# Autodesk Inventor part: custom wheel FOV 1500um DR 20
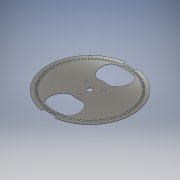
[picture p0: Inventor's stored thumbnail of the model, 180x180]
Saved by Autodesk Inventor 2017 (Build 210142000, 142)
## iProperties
Created: 2016-09
Part Number: custom wheel FOV 1500um DR 20
Material: Generic
Document SubType Name: Modeling
Designer: Radek
Density: 1 g/cm^3
Appearance: Mirror
Author: Radek
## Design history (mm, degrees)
workplane "Work Plane1"
sketch "Sketch1"
  geometry: L1 (-46.781, 4.422)-(-44.253, 4.183) reference; L2 (-44.362, 2.791)-(-46.897, 2.951) reference; L3 (-46.411, 7.351)-(-43.903, 6.954) reference; L4 (-44.099, 5.571)-(-46.619, 5.889) reference; L5 (-45.858, 10.251)-(-43.38, 9.696) reference; L6 (-43.663, 8.329)-(-46.158, 8.805) reference; L7 (-45.124, 13.11)-(-42.685, 12.401) reference; L8 (-43.054, 11.054)-(-45.514, 11.686) reference; L9 (-44.212, 15.917)-(-41.822, 15.057) reference; L10 (-42.274, 13.736)-(-44.69, 14.521) reference; L11 (-43.125, 18.662)-(-40.794, 17.653) reference; L12 (-41.329, 16.363)-(-43.69, 17.298) reference; L13 (-41.868, 21.333)-(-39.605, 20.18) reference; L14 (-40.22, 18.926)-(-42.518, 20.007) reference; L15 (-40.446, 23.92)-(-38.26, 22.627) reference; L16 (-38.952, 21.414)-(-41.178, 22.638) reference; L17 (-38.865, 26.412)-(-36.764, 24.985) reference; L18 (-37.53, 23.818)-(-39.675, 25.179) reference; L19 (-37.129, 28.801)-(-35.122, 27.244) reference; L20 (-35.961, 26.127)-(-38.016, 27.62) reference; L21 (-35.248, 31.075)-(-33.342, 29.395) reference; L22 (-34.249, 28.333)-(-36.206, 29.953) reference; L23 (-33.227, 33.227)-(-31.431, 31.431) reference; L24 (-32.403, 30.428)-(-34.254, 32.167) reference; L25 (-31.075, 35.248)-(-29.395, 33.342) reference; L26 (-30.428, 32.403)-(-32.167, 34.254) reference; L27 (-28.801, 37.129)-(-27.244, 35.122) reference; L28 (-28.333, 34.249)-(-29.953, 36.206) reference; L29 (-26.412, 38.865)-(-24.985, 36.764) reference; L30 (-26.127, 35.961)-(-27.62, 38.016) reference; L31 (-23.92, 40.446)-(-22.627, 38.26) reference; L32 (-23.818, 37.53)-(-25.179, 39.675) reference; L33 (-21.333, 41.868)-(-20.18, 39.605) reference; L34 (-21.414, 38.952)-(-22.638, 41.178) reference; L35 (-18.662, 43.125)-(-17.653, 40.794) reference; L36 (-18.926, 40.22)-(-20.007, 42.518) reference; L37 (-15.917, 44.212)-(-15.057, 41.822) reference; L38 (-16.363, 41.329)-(-17.298, 43.69) reference; L39 (-13.11, 45.124)-(-12.401, 42.685) reference; L40 (-13.736, 42.274)-(-14.521, 44.69) reference; L41 (-10.251, 45.858)-(-9.696, 43.38) reference; L42 (-11.054, 43.054)-(-11.686, 45.514) reference; L43 (-7.351, 46.411)-(-6.954, 43.903) reference; L44 (-8.329, 43.663)-(-8.805, 46.158) reference; L45 (-4.422, 46.781)-(-4.183, 44.253) reference; L46 (-5.571, 44.099)-(-5.889, 46.619) reference; L47 (-1.476, 46.967)-(-1.396, 44.428) reference; L48 (-2.791, 44.362)-(-2.951, 46.897) reference; L49 (1.476, 46.967)-(1.396, 44.428) reference; L50 (0, 44.45)-(0, 46.99) reference; L51 (4.422, 46.781)-(4.183, 44.253) reference; L52 (2.791, 44.362)-(2.951, 46.897) reference; L53 (7.351, 46.411)-(6.954, 43.903) reference; L54 (5.571, 44.099)-(5.889, 46.619) reference; L55 (10.251, 45.858)-(9.696, 43.38) reference; L56 (8.329, 43.663)-(8.805, 46.158) reference; L57 (13.11, 45.124)-(12.401, 42.685) reference; L58 (11.054, 43.054)-(11.686, 45.514) reference; L59 (15.917, 44.212)-(15.057, 41.822) reference; L60 (13.736, 42.274)-(14.521, 44.69) reference; L61 (18.662, 43.125)-(17.653, 40.794) reference; L62 (16.363, 41.329)-(17.298, 43.69) reference; L63 (21.333, 41.868)-(20.18, 39.605) reference; L64 (18.926, 40.22)-(20.007, 42.518) reference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; C1 r 50.8 at (0, 0) reference; C2 r 2.984 at (0, 0) reference; C3 r 1.524 at (0, 6.553) reference; C4 r 1.524 at (10.339, 5.969) reference; C5 r 2.984 at (0, 0) reference; C6 r 1.524 at (0, -11.938) reference; C7 r 1.524 at (-5.675, -3.277) reference; C8 r 1.524 at (-10.339, 5.969) reference; C9 r 1.524 at (5.675, -3.277) reference; C10 r 50.8 at (0, 0) reference; C11 r 1.524 at (-5.675, -3.277) reference; C12 r 1.524 at (-10.339, 5.969) reference; C13 r 1.524 at (0, 6.553) reference; C14 r 1.524 at (10.339, 5.969) reference; C15 r 1.524 at (5.675, -3.277) reference; C16 r 1.524 at (0, -11.938) reference; C17 r 2.984 at (0, 0) reference; A1 r 17.081 centre (0, 0) between (0, -17.081) and (17.081, 0) reference; A2 r 17.081 centre (0, 0) between (0, 17.081) and (-17.081, 0) reference; A3 r 43.18 centre (0, 0) between (0, 43.18) and (-43.18, 0) reference; A4 r 43.18 centre (0, 0) between (0, -43.18) and (43.18, 0) reference; A5 r 44.45 centre (0, 0) between (-44.253, 4.183) and (-44.362, 2.791) reference; A6 r 46.99 centre (0, 0) between (-46.781, 4.422) and (-46.897, 2.951) reference; A7 r 44.45 centre (0, 0) between (-43.903, 6.954) and (-44.099, 5.571) reference; A8 r 46.99 centre (0, 0) between (-46.411, 7.351) and (-46.619, 5.889) reference; A9 r 44.45 centre (0, 0) between (-43.38, 9.696) and (-43.663, 8.329) reference; A10 r 46.99 centre (0, 0) between (-45.858, 10.251) and (-46.158, 8.805) reference; A11 r 44.45 centre (0, 0) between (-42.685, 12.401) and (-43.054, 11.054) reference; A12 r 46.99 centre (0, 0) between (-45.124, 13.11) and (-45.514, 11.686) reference; A13 r 44.45 centre (0, 0) between (-41.822, 15.057) and (-42.274, 13.736) reference; A14 r 46.99 centre (0, 0) between (-44.212, 15.917) and (-44.69, 14.521) reference; A15 r 44.45 centre (0, 0) between (-40.794, 17.653) and (-41.329, 16.363) reference; A16 r 46.99 centre (0, 0) between (-43.125, 18.662) and (-43.69, 17.298) reference; A17 r 44.45 centre (0, 0) between (-39.605, 20.18) and (-40.22, 18.926) reference; A18 r 46.99 centre (0, 0) between (-41.868, 21.333) and (-42.518, 20.007) reference; A19 r 44.45 centre (0, 0) between (-38.26, 22.627) and (-38.952, 21.414) reference; A20 r 46.99 centre (0, 0) between (-40.446, 23.92) and (-41.178, 22.638) reference; A21 r 44.45 centre (0, 0) between (-36.764, 24.985) and (-37.53, 23.818) reference; A22 r 46.99 centre (0, 0) between (-38.865, 26.412) and (-39.675, 25.179) reference; A23 r 44.45 centre (0, 0) between (-35.122, 27.244) and (-35.961, 26.127) reference; A24 r 46.99 centre (0, 0) between (-37.129, 28.801) and (-38.016, 27.62) reference; A25 r 44.45 centre (0, 0) between (-33.342, 29.395) and (-34.249, 28.333) reference; A26 r 46.99 centre (0, 0) between (-35.248, 31.075) and (-36.206, 29.953) reference; A27 r 44.45 centre (0, 0) between (-31.431, 31.431) and (-32.403, 30.428) reference; A28 r 46.99 centre (0, 0) between (-33.227, 33.227) and (-34.254, 32.167) reference; A29 r 44.45 centre (0, 0) between (-29.395, 33.342) and (-30.428, 32.403) reference; A30 r 46.99 centre (0, 0) between (-31.075, 35.248) and (-32.167, 34.254) reference; A31 r 44.45 centre (0, 0) between (-27.244, 35.122) and (-28.333, 34.249) reference; A32 r 46.99 centre (0, 0) between (-28.801, 37.129) and (-29.953, 36.206) reference; A33 r 44.45 centre (0, 0) between (-24.985, 36.764) and (-26.127, 35.961) reference; A34 r 46.99 centre (0, 0) between (-26.412, 38.865) and (-27.62, 38.016) reference; A35 r 44.45 centre (0, 0) between (-22.627, 38.26) and (-23.818, 37.53) reference; A36 r 46.99 centre (0, 0) between (-23.92, 40.446) and (-25.179, 39.675) reference; A37 r 44.45 centre (0, 0) between (-20.18, 39.605) and (-21.414, 38.952) reference; A38 r 46.99 centre (0, 0) between (-21.333, 41.868) and (-22.638, 41.178) reference; A39 r 44.45 centre (0, 0) between (-17.653, 40.794) and (-18.926, 40.22) reference; A40 r 46.99 centre (0, 0) between (-18.662, 43.125) and (-20.007, 42.518) reference; A41 r 44.45 centre (0, 0) between (-15.057, 41.822) and (-16.363, 41.329) reference; A42 r 46.99 centre (0, 0) between (-15.917, 44.212) and (-17.298, 43.69) reference; A43 r 44.45 centre (0, 0) between (-12.401, 42.685) and (-13.736, 42.274) reference; A44 r 46.99 centre (0, 0) between (-13.11, 45.124) and (-14.521, 44.69) reference; A45 r 44.45 centre (0, 0) between (-9.696, 43.38) and (-11.054, 43.054) reference; A46 r 46.99 centre (0, 0) between (-10.251, 45.858) and (-11.686, 45.514) reference; A47 r 44.45 centre (0, 0) between (-6.954, 43.903) and (-8.329, 43.663) reference; A48 r 46.99 centre (0, 0) between (-7.351, 46.411) and (-8.805, 46.158) reference; A49 r 44.45 centre (0, 0) between (-4.183, 44.253) and (-5.571, 44.099) reference; A50 r 46.99 centre (0, 0) between (-4.422, 46.781) and (-5.889, 46.619) reference; A51 r 44.45 centre (0, 0) between (-1.396, 44.428) and (-2.791, 44.362) reference; A52 r 46.99 centre (0, 0) between (-1.476, 46.967) and (-2.951, 46.897) reference; A53 r 44.45 centre (0, 0) between (1.396, 44.428) and (0, 44.45) reference; A54 r 46.99 centre (0, 0) between (1.476, 46.967) and (0, 46.99) reference; A55 r 44.45 centre (0, 0) between (4.183, 44.253) and (2.791, 44.362) reference; A56 r 46.99 centre (0, 0) between (4.422, 46.781) and (2.951, 46.897) reference; A57 r 44.45 centre (0, 0) between (6.954, 43.903) and (5.571, 44.099) reference; A58 r 46.99 centre (0, 0) between (7.351, 46.411) and (5.889, 46.619) reference; A59 r 44.45 centre (0, 0) between (9.696, 43.38) and (8.329, 43.663) reference; A60 r 46.99 centre (0, 0) between (10.251, 45.858) and (8.805, 46.158) reference; A61 r 44.45 centre (0, 0) between (12.401, 42.685) and (11.054, 43.054) reference; A62 r 46.99 centre (0, 0) between (13.11, 45.124) and (11.686, 45.514) reference; A63 r 44.45 centre (0, 0) between (15.057, 41.822) and (13.736, 42.274) reference; A64 r 46.99 centre (0, 0) between (15.917, 44.212) and (14.521, 44.69) reference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; 1 further point
  constraints: 8 end point, 2 collinear, 1 parallel
extrude "Extrusion2" new body sketch "Sketch1" distance "d2" = 0.3; taper "d3" = 0 deg
sketch "Sketch2"
  geometry: L1 (-46.781, 4.422)-(-44.253, 4.183) reference; L2 (-44.362, 2.791)-(-46.897, 2.951) reference; L3 (-46.411, 7.351)-(-43.903, 6.954) reference; L4 (-44.099, 5.571)-(-46.619, 5.889) reference; L5 (-45.858, 10.251)-(-43.38, 9.696) reference; L6 (-43.663, 8.329)-(-46.158, 8.805) reference; L7 (-45.124, 13.11)-(-42.685, 12.401) reference; L8 (-43.054, 11.054)-(-45.514, 11.686) reference; L9 (-44.212, 15.917)-(-41.822, 15.057) reference; L10 (-42.274, 13.736)-(-44.69, 14.521) reference; L11 (-43.125, 18.662)-(-40.794, 17.653) reference; L12 (-41.329, 16.363)-(-43.69, 17.298) reference; L13 (-41.868, 21.333)-(-39.605, 20.18) reference; L14 (-40.22, 18.926)-(-42.518, 20.007) reference; L15 (-40.446, 23.92)-(-38.26, 22.627) reference; L16 (-38.952, 21.414)-(-41.178, 22.638) reference; L17 (-38.865, 26.412)-(-36.764, 24.985) reference; L18 (-37.53, 23.818)-(-39.675, 25.179) reference; L19 (-37.129, 28.801)-(-35.122, 27.244) reference; L20 (-35.961, 26.127)-(-38.016, 27.62) reference; L21 (-35.248, 31.075)-(-33.342, 29.395) reference; L22 (-34.249, 28.333)-(-36.206, 29.953) reference; L23 (-33.227, 33.227)-(-31.431, 31.431) reference; L24 (-32.403, 30.428)-(-34.254, 32.167) reference; L25 (-31.075, 35.248)-(-29.395, 33.342) reference; L26 (-30.428, 32.403)-(-32.167, 34.254) reference; L27 (-28.801, 37.129)-(-27.244, 35.122) reference; L28 (-28.333, 34.249)-(-29.953, 36.206) reference; L29 (-26.412, 38.865)-(-24.985, 36.764) reference; L30 (-26.127, 35.961)-(-27.62, 38.016) reference; L31 (-23.92, 40.446)-(-22.627, 38.26) reference; L32 (-23.818, 37.53)-(-25.179, 39.675) reference; L33 (-21.333, 41.868)-(-20.18, 39.605) reference; L34 (-21.414, 38.952)-(-22.638, 41.178) reference; L35 (-18.662, 43.125)-(-17.653, 40.794) reference; L36 (-18.926, 40.22)-(-20.007, 42.518) reference; L37 (-15.917, 44.212)-(-15.057, 41.822) reference; L38 (-16.363, 41.329)-(-17.298, 43.69) reference; L39 (-13.11, 45.124)-(-12.401, 42.685) reference; L40 (-13.736, 42.274)-(-14.521, 44.69) reference; L41 (-10.251, 45.858)-(-9.696, 43.38) reference; L42 (-11.054, 43.054)-(-11.686, 45.514) reference; L43 (-7.351, 46.411)-(-6.954, 43.903) reference; L44 (-8.329, 43.663)-(-8.805, 46.158) reference; L45 (-4.422, 46.781)-(-4.183, 44.253) reference; L46 (-5.571, 44.099)-(-5.889, 46.619) reference; L47 (-1.476, 46.967)-(-1.396, 44.428) reference; L48 (-2.791, 44.362)-(-2.951, 46.897) reference; L49 (1.476, 46.967)-(1.396, 44.428) reference; L50 (0, 44.45)-(0, 46.99) reference; L51 (4.422, 46.781)-(4.183, 44.253) reference; L52 (2.791, 44.362)-(2.951, 46.897) reference; L53 (7.351, 46.411)-(6.954, 43.903) reference; L54 (5.571, 44.099)-(5.889, 46.619) reference; L55 (10.251, 45.858)-(9.696, 43.38) reference; L56 (8.329, 43.663)-(8.805, 46.158) reference; L57 (13.11, 45.124)-(12.401, 42.685) reference; L58 (11.054, 43.054)-(11.686, 45.514) reference; L59 (15.917, 44.212)-(15.057, 41.822) reference; L60 (13.736, 42.274)-(14.521, 44.69) reference; L61 (18.662, 43.125)-(17.653, 40.794) reference; L62 (16.363, 41.329)-(17.298, 43.69) reference; L63 (21.333, 41.868)-(20.18, 39.605) reference; L64 (18.926, 40.22)-(20.007, 42.518) reference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; C1 r 50.8 at (0, 0) reference; C2 r 1.524 at (-5.675, -3.277) reference; C3 r 1.524 at (-10.339, 5.969) reference; C4 r 1.524 at (0, 6.553) reference; C5 r 1.524 at (10.339, 5.969) reference; C6 r 1.524 at (5.675, -3.277) reference; C7 r 1.524 at (0, -11.938) reference; C8 r 2.984 at (0, 0) reference; A1 r 44.45 centre (0, 0) between (-44.253, 4.183) and (-44.362, 2.791) reference; A2 r 46.99 centre (0, 0) between (-46.781, 4.422) and (-46.897, 2.951) reference; A3 r 44.45 centre (0, 0) between (-43.903, 6.954) and (-44.099, 5.571) reference; A4 r 46.99 centre (0, 0) between (-46.411, 7.351) and (-46.619, 5.889) reference; A5 r 44.45 centre (0, 0) between (-43.38, 9.696) and (-43.663, 8.329) reference; A6 r 46.99 centre (0, 0) between (-45.858, 10.251) and (-46.158, 8.805) reference; A7 r 44.45 centre (0, 0) between (-42.685, 12.401) and (-43.054, 11.054) reference; A8 r 46.99 centre (0, 0) between (-45.124, 13.11) and (-45.514, 11.686) reference; A9 r 44.45 centre (0, 0) between (-41.822, 15.057) and (-42.274, 13.736) reference; A10 r 46.99 centre (0, 0) between (-44.212, 15.917) and (-44.69, 14.521) reference; A11 r 44.45 centre (0, 0) between (-40.794, 17.653) and (-41.329, 16.363) reference; A12 r 46.99 centre (0, 0) between (-43.125, 18.662) and (-43.69, 17.298) reference; A13 r 44.45 centre (0, 0) between (-39.605, 20.18) and (-40.22, 18.926) reference; A14 r 46.99 centre (0, 0) between (-41.868, 21.333) and (-42.518, 20.007) reference; A15 r 44.45 centre (0, 0) between (-38.26, 22.627) and (-38.952, 21.414) reference; A16 r 46.99 centre (0, 0) between (-40.446, 23.92) and (-41.178, 22.638) reference; A17 r 44.45 centre (0, 0) between (-36.764, 24.985) and (-37.53, 23.818) reference; A18 r 46.99 centre (0, 0) between (-38.865, 26.412) and (-39.675, 25.179) reference; A19 r 44.45 centre (0, 0) between (-35.122, 27.244) and (-35.961, 26.127) reference; A20 r 46.99 centre (0, 0) between (-37.129, 28.801) and (-38.016, 27.62) reference; A21 r 44.45 centre (0, 0) between (-33.342, 29.395) and (-34.249, 28.333) reference; A22 r 46.99 centre (0, 0) between (-35.248, 31.075) and (-36.206, 29.953) reference; A23 r 44.45 centre (0, 0) between (-31.431, 31.431) and (-32.403, 30.428) reference; A24 r 46.99 centre (0, 0) between (-33.227, 33.227) and (-34.254, 32.167) reference; A25 r 44.45 centre (0, 0) between (-29.395, 33.342) and (-30.428, 32.403) reference; A26 r 46.99 centre (0, 0) between (-31.075, 35.248) and (-32.167, 34.254) reference; A27 r 44.45 centre (0, 0) between (-27.244, 35.122) and (-28.333, 34.249) reference; A28 r 46.99 centre (0, 0) between (-28.801, 37.129) and (-29.953, 36.206) reference; A29 r 44.45 centre (0, 0) between (-24.985, 36.764) and (-26.127, 35.961) reference; A30 r 46.99 centre (0, 0) between (-26.412, 38.865) and (-27.62, 38.016) reference; A31 r 44.45 centre (0, 0) between (-22.627, 38.26) and (-23.818, 37.53) reference; A32 r 46.99 centre (0, 0) between (-23.92, 40.446) and (-25.179, 39.675) reference; A33 r 44.45 centre (0, 0) between (-20.18, 39.605) and (-21.414, 38.952) reference; A34 r 46.99 centre (0, 0) between (-21.333, 41.868) and (-22.638, 41.178) reference; A35 r 44.45 centre (0, 0) between (-17.653, 40.794) and (-18.926, 40.22) reference; A36 r 46.99 centre (0, 0) between (-18.662, 43.125) and (-20.007, 42.518) reference; A37 r 44.45 centre (0, 0) between (-15.057, 41.822) and (-16.363, 41.329) reference; A38 r 46.99 centre (0, 0) between (-15.917, 44.212) and (-17.298, 43.69) reference; A39 r 44.45 centre (0, 0) between (-12.401, 42.685) and (-13.736, 42.274) reference; A40 r 46.99 centre (0, 0) between (-13.11, 45.124) and (-14.521, 44.69) reference; A41 r 44.45 centre (0, 0) between (-9.696, 43.38) and (-11.054, 43.054) reference; A42 r 46.99 centre (0, 0) between (-10.251, 45.858) and (-11.686, 45.514) reference; A43 r 44.45 centre (0, 0) between (-6.954, 43.903) and (-8.329, 43.663) reference; A44 r 46.99 centre (0, 0) between (-7.351, 46.411) and (-8.805, 46.158) reference; A45 r 44.45 centre (0, 0) between (-4.183, 44.253) and (-5.571, 44.099) reference; A46 r 46.99 centre (0, 0) between (-4.422, 46.781) and (-5.889, 46.619) reference; A47 r 44.45 centre (0, 0) between (-1.396, 44.428) and (-2.791, 44.362) reference; A48 r 46.99 centre (0, 0) between (-1.476, 46.967) and (-2.951, 46.897) reference; A49 r 44.45 centre (0, 0) between (1.396, 44.428) and (0, 44.45) reference; A50 r 46.99 centre (0, 0) between (1.476, 46.967) and (0, 46.99) reference; A51 r 44.45 centre (0, 0) between (4.183, 44.253) and (2.791, 44.362) reference; A52 r 46.99 centre (0, 0) between (4.422, 46.781) and (2.951, 46.897) reference; A53 r 44.45 centre (0, 0) between (6.954, 43.903) and (5.571, 44.099) reference; A54 r 46.99 centre (0, 0) between (7.351, 46.411) and (5.889, 46.619) reference; A55 r 44.45 centre (0, 0) between (9.696, 43.38) and (8.329, 43.663) reference; A56 r 46.99 centre (0, 0) between (10.251, 45.858) and (8.805, 46.158) reference; A57 r 44.45 centre (0, 0) between (12.401, 42.685) and (11.054, 43.054) reference; A58 r 46.99 centre (0, 0) between (13.11, 45.124) and (11.686, 45.514) reference; A59 r 44.45 centre (0, 0) between (15.057, 41.822) and (13.736, 42.274) reference; A60 r 46.99 centre (0, 0) between (15.917, 44.212) and (14.521, 44.69) reference; A61 r 44.45 centre (0, 0) between (17.653, 40.794) and (16.363, 41.329) reference; A62 r 46.99 centre (0, 0) between (18.662, 43.125) and (17.298, 43.69) reference; A63 r 44.45 centre (0, 0) between (20.18, 39.605) and (18.926, 40.22) reference; A64 r 46.99 centre (0, 0) between (21.333, 41.868) and (20.007, 42.518) reference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; 1 further point
  constraints: 8 end point, 1 collinear
extrude "Extrusion3" cut sketch "Sketch2" stored distance "d4" = 0.254; taper "d5" = 0 deg
sketch "Sketch3" dims "d20" = 9.26667 (= 0.5 x holediameter), "d21" = 13.10505 (= 1.41421 x d20)
  geometry: L1 (-10.339, 5.969)-(10.339, 5.969); L2 (0, 0)-(50.8, 0); L3 (0, 44.45)-(0, 46.99) reference; L4 (0, 0)-(0, 50.8); L5 (0, 30)-(0, 16.895); L6 (0, 50.165)-(0, 48.26) reference; L7 (-48.26, 0)-(-50.165, 0) reference; L8 (0, 0)-(19.371, 28.772); L9 (0, 50.8)-(0, 50.165); L10 (4.373, 16.319)-(11.156, 41.636); L11 (-4.373, 16.319)-(-11.156, 41.636); C1 r 2.984 at (0, 0) reference; C2 r 15.25 at (0, 0); C3 r 1.524 at (-10.339, 5.969) reference; C4 r 1.524 at (0, -11.938) reference; C5 r 1.524 at (10.339, 5.969) reference; C6 r 1.524 at (-5.675, -3.277) reference; C7 r 1.524 at (5.675, -3.277) reference; A1 r 50.8 centre (0, 0) between (50.8, 0) and (0, 50.8) reference; A2 r 48.26 centre (0, 0) between (0, 48.26) and (-48.26, 0) reference; A3 r 50.165 centre (0, 0) between (0, 50.165) and (-50.165, 0) reference; A4 r 50.165 centre (0, 0) between (-20.154, -45.939) and (22.037, -45.066); A5 r 48.26 centre (0, 0) between (-19.033, -44.348) and (20.956, -43.472); 3 further points; 3 other entities
  constraints: 16 end point, 8 point on circle, 3 centre point, 3 coincident, 2 midpoint, 2 vertical, 1 collinear, 1 horizontal, 1 parallel, 1 point on line, 1 vertical alignment, 19 other
  dimensions: "d9" = 30.5 diameter of C2; "d18" = 0 distance between parallel lines of L4 L5; "d19" = 30 distance of point (0, 0) L5.start (= offaxis); "d24" = 15 deg dimension on point (0, 0) L5.start point (-7.765, 28.978) (= 0.5 x angle); "d28" = 15 deg dimension on point (0, 0) point (7.765, 28.978) L5.start (= 0.5 x angle); "d32" = 0.635 distance of L4.end L6.start (derived)
extrude "Extrusion7" cut sketch "Sketch3" stored distance "d40" = 10; taper "d41" = 0 deg
sketch "Sketch4"
  geometry: L1 (-11.156, 41.636)-(-4.373, 16.319) reference; L2 (4.373, 16.319)-(11.156, 41.636) reference; L3 (11.156, 41.636)-(4.373, 16.319) reference; L4 (-4.373, 16.319)-(-11.156, 41.636) reference; L5 (-4.373, 16.319)-(-11.156, 41.636); L6 (4.373, 16.319)-(11.156, 41.636); C1 r 2.984 at (0, 0) reference; C2 r 50.8 at (0, 0) reference; A1 r 16.895 centre (0, 0) between (4.373, 16.319) and (-4.373, 16.319); A2 r 43.105 centre (0, 0) between (11.156, 41.636) and (-11.156, 41.636); 3 further points; 2 other entities
  constraints: 4 end point, 4 point on circle, 2 centre point, 2 coincident, 2 collinear, 2 other
extrude "Extrusion8" cut sketch "Sketch4" stored distance "d42" = 10; taper "d43" = 0 deg
sketch "Sketch5"
  geometry: L1 (0, 0)-(-7.947, 50.175); L2 (0, 0)-(7.947, 50.175); L3 (7.524, 47.508)-(7.837, 49.483); L4 (-7.524, 47.508)-(-7.837, 49.483); L5 (6.954, 43.903)-(7.351, 46.411) reference; L6 (4.422, 46.781)-(4.183, 44.253) reference; L7 (7.351, 46.411)-(6.954, 43.903) reference; C1 r 2.984 at (0, 0) reference; A1 r 50.8 centre (0, 0) between (-7.947, 50.175) and (7.947, 50.175) reference; A2 r 16.895 centre (0, 0) between (4.373, 16.319) and (-4.373, 16.319) reference; A3 r 43.105 centre (0, 0) between (11.156, 41.636) and (-11.156, 41.636) reference; A4 r 48.1 centre (0, 0) between (7.524, 47.508) and (-7.524, 47.508); A5 r 50.1 centre (0, 0) between (7.837, 49.483) and (-7.837, 49.483); 4 further points; 2 other entities
  constraints: 8 end point, 6 point on circle, 3 point on line, 2 centre point, 2 coincident, 2 collinear, 1 midpoint, 8 other
  dimensions: "d44" = 0.7 radial gap between concentric circles of A1 A5; "d45" = 2 radial gap between concentric circles of A5 A4; "d53" = 18 deg angle of L1 L2
extrude "Extrusion9" cut sketch "Sketch5" stored distance "d46" = 10; taper "d47" = 0 deg
pattern_circular "Circular Pattern3" dims angle "d49" = 360 deg
sketch "Sketch6"
  geometry: L1 (16.895, 0)-(16.319, 0) reference; L2 (41.636, 0)-(43.105, 0) reference; L3 (16.319, -0.3)-(16.895, -0.3) reference; L4 (43.105, -0.3)-(41.636, -0.3) reference; L5 (-50.8, 0)-(50.8, 0) reference; L6 (-50.8, -0.3)-(50.8, -0.3) reference; L7 (16.895, 0)-(43.105, 0); L8 (16.895, -0.3)-(43.105, -0.3); L9 (30, -0.3)-(30, 0); L10 (30, -0.15)-(32.935, -3.085); 1 further point
  constraints: 8 end point, 3 midpoint, 1 collinear, 1 parallel
  dimensions: "d51" = 135 deg angle of L10 L9
workaxis "Work Axis1"
workplane "Work Plane3"
  workplane "Work Plane2"
sketch "Sketch7"
  geometry: L1 (0, -11.938)-(-10.339, 5.969); C1 r 1.524 at (0, -11.938) reference; C2 r 1.524 at (-10.339, 5.969) reference; C3 r 2.984 at (0, 0) reference; C4 r 10.414 at (0, 0); 2 further points
  constraints: 2 end point, 1 centre point, 1 coincident, 1 tangent, 1 other
extrude "Extrusion11" cut sketch "Sketch7" stored distance "d57" = 10; taper "d58" = 0 deg
sketch "Sketch8"
  geometry: L1 (7.524, -47.508)-(7.837, -49.483) reference; L2 (-7.837, -49.483)-(-7.524, -47.508) reference; L3 (7.837, 49.483)-(7.524, 47.508) reference; L4 (-7.524, 47.508)-(-7.837, 49.483) reference; L5 (-46.967, -1.476)-(-44.428, -1.396) reference; L6 (-44.428, -1.396)-(-44.362, -2.791) reference; L7 (-44.362, -2.791)-(-46.897, -2.951) reference; L8 (-46.897, -2.951)-(-46.967, -1.476) reference; L9 (-46.781, -4.422)-(-44.253, -4.183) reference; L10 (-44.253, -4.183)-(-44.099, -5.571) reference; L11 (-44.099, -5.571)-(-46.619, -5.889) reference; L12 (-46.619, -5.889)-(-46.781, -4.422) reference; L13 (-46.411, -7.351)-(-43.903, -6.954) reference; L14 (-43.903, -6.954)-(-43.663, -8.329) reference; L15 (-43.663, -8.329)-(-46.158, -8.805) reference; L16 (-46.158, -8.805)-(-46.411, -7.351) reference; L17 (-45.858, -10.251)-(-43.38, -9.696) reference; L18 (-43.38, -9.696)-(-43.054, -11.054) reference; L19 (-43.054, -11.054)-(-45.514, -11.686) reference; L20 (-45.514, -11.686)-(-45.858, -10.251) reference; L21 (-45.124, -13.11)-(-42.685, -12.401) reference; L22 (-42.685, -12.401)-(-42.274, -13.736) reference; L23 (-42.274, -13.736)-(-44.69, -14.521) reference; L24 (-44.69, -14.521)-(-45.124, -13.11) reference; L25 (-44.212, -15.917)-(-41.822, -15.057) reference; L26 (-41.822, -15.057)-(-41.329, -16.363) reference; L27 (-41.329, -16.363)-(-43.69, -17.298) reference; L28 (-43.69, -17.298)-(-44.212, -15.917) reference; L29 (-43.125, -18.662)-(-40.794, -17.653) reference; L30 (-40.794, -17.653)-(-40.22, -18.926) reference; L31 (-40.22, -18.926)-(-42.518, -20.007) reference; L32 (-42.518, -20.007)-(-43.125, -18.662) reference; L33 (-41.868, -21.333)-(-39.605, -20.18) reference; L34 (-39.605, -20.18)-(-38.952, -21.414) reference; L35 (-38.952, -21.414)-(-41.178, -22.638) reference; L36 (-41.178, -22.638)-(-41.868, -21.333) reference; L37 (-40.446, -23.92)-(-38.26, -22.627) reference; L38 (-38.26, -22.627)-(-37.53, -23.818) reference; L39 (-37.53, -23.818)-(-39.675, -25.179) reference; L40 (-39.675, -25.179)-(-40.446, -23.92) reference; L41 (-38.865, -26.412)-(-36.764, -24.985) reference; L42 (-36.764, -24.985)-(-35.961, -26.127) reference; L43 (-35.961, -26.127)-(-38.016, -27.62) reference; L44 (-38.016, -27.62)-(-38.865, -26.412) reference; L45 (-37.129, -28.801)-(-35.122, -27.244) reference; L46 (-35.122, -27.244)-(-34.249, -28.333) reference; L47 (-34.249, -28.333)-(-36.206, -29.953) reference; L48 (-36.206, -29.953)-(-37.129, -28.801) reference; L49 (-35.248, -31.075)-(-33.342, -29.395) reference; L50 (-33.342, -29.395)-(-32.403, -30.428) reference; L51 (-32.403, -30.428)-(-34.254, -32.167) reference; L52 (-34.254, -32.167)-(-35.248, -31.075) reference; L53 (-33.227, -33.227)-(-31.431, -31.431) reference; L54 (-31.431, -31.431)-(-30.428, -32.403) reference; L55 (-30.428, -32.403)-(-32.167, -34.254) reference; L56 (-32.167, -34.254)-(-33.227, -33.227) reference; L57 (-31.075, -35.248)-(-29.395, -33.342) reference; L58 (-29.395, -33.342)-(-28.333, -34.249) reference; L59 (-28.333, -34.249)-(-29.953, -36.206) reference; L60 (-29.953, -36.206)-(-31.075, -35.248) reference; L61 (-28.801, -37.129)-(-27.244, -35.122) reference; L62 (-27.244, -35.122)-(-26.127, -35.961) reference; L63 (-26.127, -35.961)-(-27.62, -38.016) reference; L64 (-27.62, -38.016)-(-28.801, -37.129) reference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; C1 r 2.984 at (0, 0) reference; C2 r 1.524 at (5.675, -3.277) reference; C3 r 1.524 at (-10.339, 5.969) reference; C4 r 1.524 at (-5.675, -3.277) reference; C5 r 1.524 at (0, -11.938) reference; C6 r 1.524 at (10.339, 5.969) reference; C7 r 1.524 at (0, 6.553) reference; C8 r 50.8 at (0, 0) reference; C9 r 2.984 at (0, 0) reference; A1 r 16.895 centre (0, 0) between (-4.373, -16.319) and (4.373, -16.319) reference; A2 r 43.105 centre (0, 0) between (-11.156, -41.636) and (11.156, -41.636) reference; A3 r 50.1 centre (0, 0) between (-7.837, -49.483) and (7.837, -49.483) reference; A4 r 48.1 centre (0, 0) between (-7.524, -47.508) and (7.524, -47.508) reference; A5 r 48.1 centre (0, 0) between (7.524, 47.508) and (-7.524, 47.508) reference; A6 r 50.1 centre (0, 0) between (7.837, 49.483) and (-7.837, 49.483) reference; A7 r 43.105 centre (0, 0) between (11.156, 41.636) and (-11.156, 41.636) reference; A8 r 16.895 centre (0, 0) between (4.373, 16.319) and (-4.373, 16.319) reference; A9 r 43.105 centre (0, 0) between (-11.156, -41.636) and (11.156, -41.636); A10 r 16.895 centre (0, 0) between (-4.373, -16.319) and (4.373, -16.319); 4 further points; 5 other entities
  constraints: 8 end point, 4 point on circle, 2 centre point, 2 coincident, 2 collinear, 2 point on line, 6 other
extrude "Extrusion12" cut sketch "Sketch8" stored distance "d59" = 10; taper "d60" = 0 deg
pattern_circular "Circular Pattern4" dims angle "d62" = 360 deg
sketch "Sketch9"
  geometry: L1 (-44.45, 0)-(-46.99, 0) reference; L2 (-46.99, 0)-(-46.967, 1.476) reference; L3 (-46.967, 1.476)-(-44.428, 1.396) reference; L4 (-44.428, 1.396)-(-44.45, 0) reference; L5 (-46.781, 4.422)-(-44.253, 4.183) reference; L6 (-44.253, 4.183)-(-44.362, 2.791) reference; L7 (-44.362, 2.791)-(-46.897, 2.951) reference; L8 (-46.897, 2.951)-(-46.781, 4.422) reference; L9 (-46.411, 7.351)-(-43.903, 6.954) reference; L10 (-43.903, 6.954)-(-44.099, 5.571) reference; L11 (-44.099, 5.571)-(-46.619, 5.889) reference; L12 (-46.619, 5.889)-(-46.411, 7.351) reference; L13 (-45.858, 10.251)-(-43.38, 9.696) reference; L14 (-43.38, 9.696)-(-43.663, 8.329) reference; L15 (-43.663, 8.329)-(-46.158, 8.805) reference; L16 (-46.158, 8.805)-(-45.858, 10.251) reference; L17 (-45.124, 13.11)-(-42.685, 12.401) reference; L18 (-42.685, 12.401)-(-43.054, 11.054) reference; L19 (-43.054, 11.054)-(-45.514, 11.686) reference; L20 (-45.514, 11.686)-(-45.124, 13.11) reference; L21 (-44.212, 15.917)-(-41.822, 15.057) reference; L22 (-41.822, 15.057)-(-42.274, 13.736) reference; L23 (-42.274, 13.736)-(-44.69, 14.521) reference; L24 (-44.69, 14.521)-(-44.212, 15.917) reference; L25 (-43.125, 18.662)-(-40.794, 17.653) reference; L26 (-40.794, 17.653)-(-41.329, 16.363) reference; L27 (-41.329, 16.363)-(-43.69, 17.298) reference; L28 (-43.69, 17.298)-(-43.125, 18.662) reference; L29 (-41.868, 21.333)-(-39.605, 20.18) reference; L30 (-39.605, 20.18)-(-40.22, 18.926) reference; L31 (-40.22, 18.926)-(-42.518, 20.007) reference; L32 (-42.518, 20.007)-(-41.868, 21.333) reference; L33 (-40.446, 23.92)-(-38.26, 22.627) reference; L34 (-38.26, 22.627)-(-38.952, 21.414) reference; L35 (-38.952, 21.414)-(-41.178, 22.638) reference; L36 (-41.178, 22.638)-(-40.446, 23.92) reference; L37 (-38.865, 26.412)-(-36.764, 24.985) reference; L38 (-36.764, 24.985)-(-37.53, 23.818) reference; L39 (-37.53, 23.818)-(-39.675, 25.179) reference; L40 (-39.675, 25.179)-(-38.865, 26.412) reference; L41 (-37.129, 28.801)-(-35.122, 27.244) reference; L42 (-35.122, 27.244)-(-35.961, 26.127) reference; L43 (-35.961, 26.127)-(-38.016, 27.62) reference; L44 (-38.016, 27.62)-(-37.129, 28.801) reference; L45 (-35.248, 31.075)-(-33.342, 29.395) reference; L46 (-33.342, 29.395)-(-34.249, 28.333) reference; L47 (-34.249, 28.333)-(-36.206, 29.953) reference; L48 (-36.206, 29.953)-(-35.248, 31.075) reference; L49 (-33.227, 33.227)-(-31.431, 31.431) reference; L50 (-31.431, 31.431)-(-32.403, 30.428) reference; L51 (-32.403, 30.428)-(-34.254, 32.167) reference; L52 (-34.254, 32.167)-(-33.227, 33.227) reference; L53 (-31.075, 35.248)-(-29.395, 33.342) reference; L54 (-29.395, 33.342)-(-30.428, 32.403) reference; L55 (-30.428, 32.403)-(-32.167, 34.254) reference; L56 (-32.167, 34.254)-(-31.075, 35.248) reference; L57 (-28.801, 37.129)-(-27.244, 35.122) reference; L58 (-27.244, 35.122)-(-28.333, 34.249) reference; L59 (-28.333, 34.249)-(-29.953, 36.206) reference; L60 (-29.953, 36.206)-(-28.801, 37.129) reference; L61 (-26.412, 38.865)-(-24.985, 36.764) reference; L62 (-24.985, 36.764)-(-26.127, 35.961) reference; L63 (-26.127, 35.961)-(-27.62, 38.016) reference; L64 (-27.62, 38.016)-(-26.412, 38.865) reference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; C1 r 50.8 at (0, 0) reference; C2 r 1.524 at (0, 6.553) reference; C3 r 1.524 at (10.339, 5.969) reference; C4 r 1.524 at (0, -11.938) reference; C5 r 1.524 at (-5.675, -3.277) reference; C6 r 1.524 at (-10.339, 5.969) reference; C7 r 1.524 at (5.675, -3.277) reference; C8 r 2.984 at (0, 0) reference; C9 r 2.984 at (0, 0) reference; A1 r 16.895 centre (0, 0) between (4.373, 16.319) and (-4.373, 16.319) reference; A2 r 48.1 centre (0, 0) between (7.524, 47.508) and (-7.524, 47.508) reference; A3 r 50.1 centre (0, 0) between (7.837, 49.483) and (-7.837, 49.483) reference; A4 r 50.1 centre (0, 0) between (-7.837, -49.483) and (7.837, -49.483) reference; A5 r 48.1 centre (0, 0) between (-7.524, -47.508) and (7.524, -47.508) reference; A6 r 43.105 centre (0, 0) between (-11.156, -41.636) and (11.156, -41.636) reference; A7 r 16.895 centre (0, 0) between (-4.373, -16.319) and (4.373, -16.319) reference; A8 r 48.1 centre (0, 0) between (-7.524, -47.508) and (7.524, -47.508); A9 r 55.8 centre (0, 0) between (-8.729, -55.113) and (8.729, -55.113); A10 r 43.105 centre (0, 0) between (11.156, 41.636) and (-11.156, 41.636) reference; 5 further points; 4 other entities
  constraints: 8 end point, 4 point on circle, 4 point on line, 2 centre point, 2 coincident, 2 collinear, 4 other
  dimensions: "d64" = 5 radial gap between concentric circles of C1 A9
extrude "Extrusion13" cut sketch "Sketch9" stored distance "d65" = 10; taper "d66" = 0 deg
pattern_circular "Circular Pattern5" dims angle "d68" = 360 deg
fillet "Fillet1" dims "d70" = 0.5 (derived)
fillet "Fillet3" dims "d72" = 0.5 (derived)
pattern_circular "Circular Pattern7" dims angle "d77" = 360 deg
sketch "Sketch10"
  geometry: C1 r 1.524 at (-5.675, -3.277) reference; C2 r 1.524 at (0, 6.553) reference; C3 r 1.524 at (5.675, -3.277) reference; 1 further point
extrude "Extrusion14" join sketch "Sketch10" stored distance "d79" = 10; taper "d80" = 0 deg
body "Solid2"
pattern_circular "Circular Pattern1" dims angle "d7" = 360 deg
pattern_circular "Circular Pattern6" dims angle "d74" = 360 deg
node "Reference1"
node "Reference2"
node "Reference3"
node "Reference4"
node "Reference5"
node "Reference6"
node "Reference7"
node "Reference8"
node "Reference9"
node "Reference10"
node "Reference11"
node "Reference12"
node "Reference13"
node "Reference14"
node "Reference15"
node "Reference16"
node "Reference17"
node "Reference18"
node "Reference19"
node "Projected Loop1"
node "Projected Loop2"
other parameters: "d12" = 9.66667 (computed from ftube, FOV), "FOV" = 1.5 [user parameter; used in 2 equation terms], "dutycycle" = 3.63311 (computed from holelength, offaxis) [user parameter], "offaxis" = 30 [user parameter; used in 4 equation terms], "angle" = 30 deg (computed from holediameter, holelength, offaxis) [user parameter; used in 2 equation terms], "holelength" = 34.2413 (computed from dutyratio, offaxis, holediameter) [user parameter; used in 2 equation terms], "holediameter" = 18.53333 (computed from FOV, ftube) [user parameter; used in 3 equation terms], "dutyratio" = 2 [user parameter; used in 1 equation term], "d52" = 45 deg, "minradius" = 0.5 [user parameter]
